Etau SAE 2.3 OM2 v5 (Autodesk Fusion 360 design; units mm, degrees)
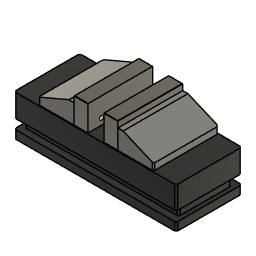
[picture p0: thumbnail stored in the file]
parameter "ouverture" = 20
base_feature "Fonction de base1"
base_feature "Fonction de base1"
base_feature "Fonction de base1"
work_plane "Plan de construction"
position "Position1" TranslateAlongZ 10 (= "ouverture / 2") TranslateAlongZ -10 (= "-ouverture / 2")
sketch "Esquisse1" plane through (0, 0, 0) normal (0, 0, 1) x axis (1, 0, 0)
  line L1 (-40, -17.5) -> (40, -17.5)
  line L2 (-40, 17.5) -> (-40, -17.5)
  line L3 (40, 17.5) -> (-40, 17.5)
  line L4 (40, -17.5) -> (40, 17.5)
  line L5 (-40, 17.5) -> (40, -17.5)
  line L6 (40, 17.5) -> (-40, -17.5)
  point P6 (0, 0)
  point P1 (0, 0)
  point P4 (-40, 17.5)
  point P5 (40, 17.5)
  point P3 (-40, -17.5)
  horizontal L1
  perpendicular L1 L2
  parallel L1 L3
  parallel L2 L4
  coincident L5 P6
  coincident L6 P6
  coincident P1 P6
  dimension "d1" distance P4 P5 = 80
  dimension "d2" distance P3 P4 = 35
extrude "Extrusion1" new body sketch "Esquisse1" profile of L1 L2 L3 L4 distance 10
sketch "Esquisse2" plane through (0, 0, 5) normal (0, 0, 1) x axis (-1, 0, 0)
  line L1 (40, -17.5) -> (-40, -17.5)
  line L2 (40, 17.5) -> (40, -17.5)
  line L3 (-40, 17.5) -> (40, 17.5)
  line L4 (-40, -17.5) -> (-40, 17.5)
  line L5 (7, 15.5) -> (-7, 15.5)
  line L6 (7, 1.5) -> (7, 15.5)
  line L7 (-7, 1.5) -> (7, 1.5)
  line L8 (-7, 15.5) -> (-7, 1.5)
  line L9 (7, 1.5) -> (-7, 15.5)
  line L10 (-7, 1.5) -> (7, 15.5)
  point P10 (0, 8.5)
  point P8 (7, 1.5)
  point P9 (-7, 1.5)
  point P7 (7, 15.5)
  horizontal L5
  perpendicular L5 L6
  parallel L5 L7
  parallel L6 L8
  coincident L9 P10
  coincident L10 P10
  dimension "d5" distance P8 P9 = 14
  dimension "d6" distance P7 P8 = 14 (= "d5")
  dimension "d7" distance L3 P10 = 9
extrude "Extrusion2" add sketch "Esquisse2" profile of L5 L6 L7 L8 along normal blind 2.4
sketch "Esquisse3" plane through (0, 0, 5) normal (0, 0, 1) x axis (-1, 0, 0)
  line L1 (-7, 15.5) -> (-7, 1.5)
  line L2 (7, 15.5) -> (-7, 15.5)
  line L3 (7, 1.5) -> (7, 15.5)
  line L4 (-7, 1.5) -> (7, 1.5)
  line L5 (40, -17.5) -> (-40, -17.5)
  line L6 (40, 17.5) -> (40, -17.5)
  line L7 (-40, 17.5) -> (40, 17.5)
  line L8 (-40, -17.5) -> (-40, 17.5)
  point P10 (23, 9.5)
  point P11 (-23, 9.5)
  point P1 (0, 0)
  horizontal P10 P11
  dimension "d11" distance P1 P10 = 23
  dimension "d12_1" distance P1 P11 = 23 (= "d11")
  dimension "d13_1" distance L7 P10 = 8
hole "Perçage" HoleDepth 11 HoleDiameter 5.035
sketch "Esquisse4" plane through (0, 17.5, 0) normal (0, 1, 0) x axis (-1, 0, 0)
  line L1 (40, 5) -> (40, -5)
  line L2 (-40, 5) -> (40, 5)
  line L3 (-40, -5) -> (-40, 5)
  line L4 (40, -5) -> (-40, -5)
  line L5 (40, 5) -> (-40, 5)
  line L6 (40, 0) -> (40, 5)
  line L7 (-40, 0) -> (40, 0)
  line L8 (-40, 5) -> (-40, 0)
  point P8 (40, 0)
  point P4 (-40, 5)
  point P6 (-40, 5)
  point P9 (-40, 0)
  horizontal L5
  vertical L6
  horizontal L7
  vertical L8
  coincident L1 P8
  coincident P4 P6
  dimension "d17" distance P6 P9 = 5
extrude "Extrusion3" add sketch "Esquisse4" profile of L1 L2 L3 L5 L6 L7 L8 along normal blind 4
position "Position2"
extrude "Extrusion4" cut of existing geometry blind -6
extrude "Extrusion5" cut of existing geometry blind -2
mirror_component "MirrorComponent1"
derived_instance "DerivedInstance1"
as_built_joint "Réelle5"
as_built_joint "Réelle6"
extrude "Extrusion1" add of existing geometry blind 7
extrude "Extrusion6" add of existing geometry blind 7
joint "Assembler1" alignOffsetX 0 alignOffsetY 0 alignOffsetZ 0
joint "Assembler2" alignOffsetX 0 alignOffsetY 0 alignOffsetZ 0
position "Position3" TranslateAlongZ -10 (= "-ouverture / 2") TranslateAlongZ 10 (= "ouverture / 2")
chamfer "Chanfrein1" distance 0.25
chamfer "Chanfrein1" distance 0.25
offset_faces "DécalerLesFaces1" distance -1.5
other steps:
derived_base_feature "Fonction de base dérivée"
offset_faces "DécalerLesFaces1" distance -1.5
thread "Filetage" ThreadOffset 0 ThreadDepth 10
create_component "CreateComponent3"
create_component "CreateComponent4"
create_component "CreateComponent5"
create_component "CreateComponent6"
create_component "CreateComponent7"
joint_origin "JointOrigin2"
joint_origin "JointOrigin3"
joint_origin "JointOrigin2"
joint_origin "JointOrigin4"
